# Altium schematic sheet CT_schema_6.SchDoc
size 368 x 245 mm
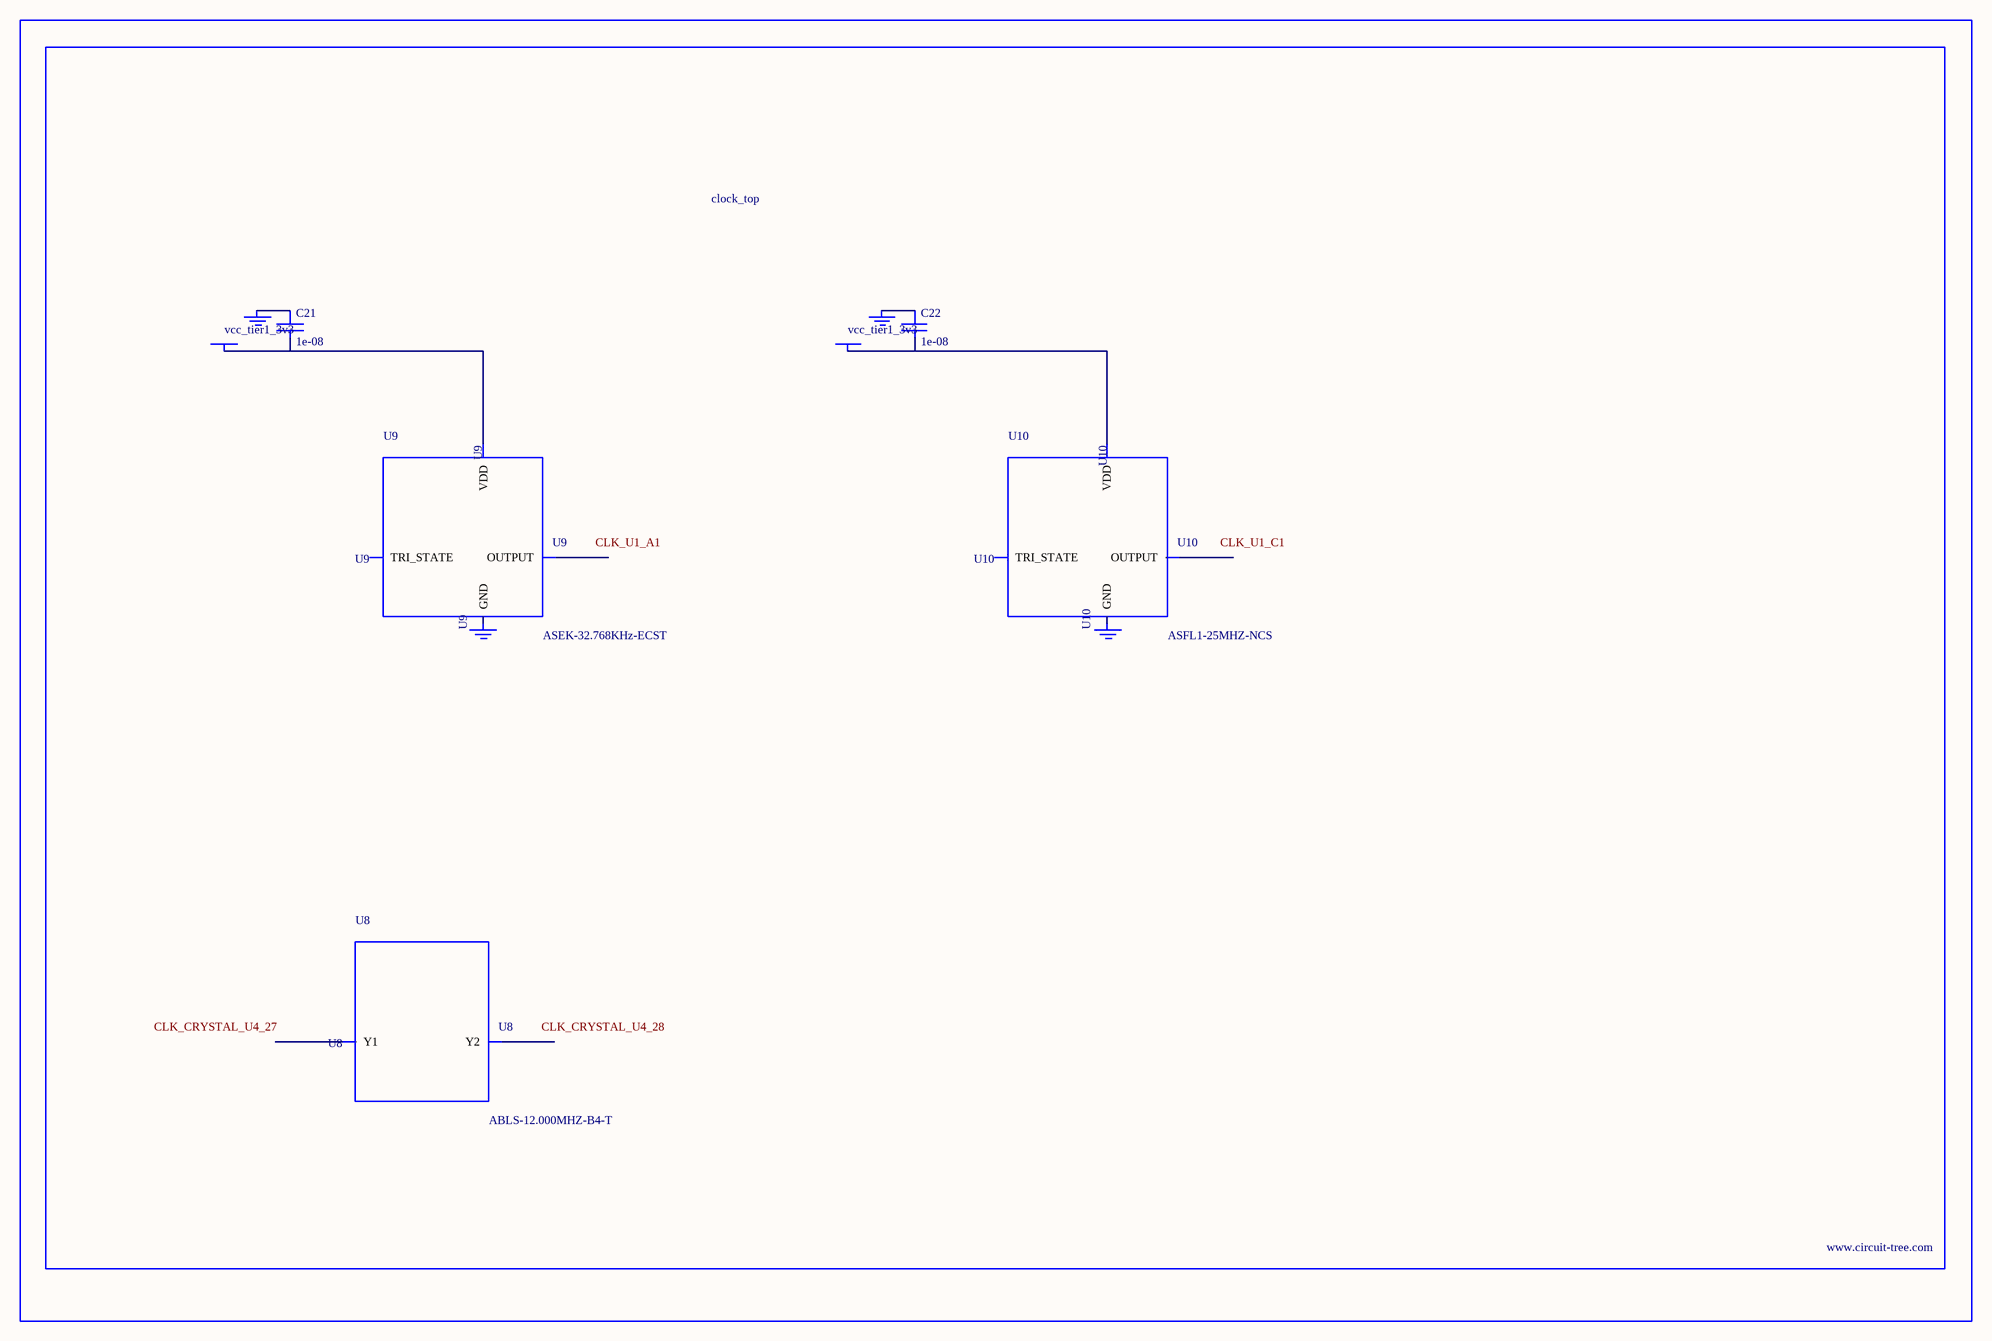
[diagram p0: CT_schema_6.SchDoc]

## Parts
BORDER5  (no value)
C21  1e-08  [C0402]
C22  1e-08  [C0402]
GND_INSTANCE_5_0  (no value)
GND_INSTANCE_5_1  (no value)
GND_INSTANCE_5_2  (no value)
GND_INSTANCE_5_3  (no value)
POWER_INSTANCE_5_0  vcc_tier1_3v3
POWER_INSTANCE_5_1  vcc_tier1_3v3
U8  ABLS-12.000MHZ-B4-T  [ABLS-12.000MHZ-B4-T]
U9  ASEK-32.768KHz-ECST  [ASEK]
U10  ASFL1-25MHZ-NCS  [ASFL1]

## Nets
NetC21_1: C21.1 GND_INSTANCE_5_0.0(GND)
NetC21_2: C21.2 POWER_INSTANCE_5_0.0(PWR) U9.4(VDD)
NetC22_1: C22.1 GND_INSTANCE_5_2.0(GND)
NetC22_2: C22.2 POWER_INSTANCE_5_1.0(PWR) U10.4(VDD)

Not connected (* = marked no-connect by the designer): GND_INSTANCE_5_1 0(GND); GND_INSTANCE_5_3 0(GND); U8 1(Y1) 2(Y2); U9 1(TRI_STATE) 2(GND) 3(OUTPUT); U10 1(TRI_STATE) 2(GND) 3(OUTPUT)

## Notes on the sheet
- Labels drawn without touching a wire or pin: CLK_CRYSTAL_U4_27, CLK_CRYSTAL_U4_28, CLK_U1_A1, CLK_U1_C1

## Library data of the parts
BORDER5 = BORDER_PAGE5
C21 C22 = C0402C103K3RAC
GND_INSTANCE_5_0-GND_INSTANCE_5_3 = GND
POWER_INSTANCE_5_0 POWER_INSTANCE_5_1 = PWR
